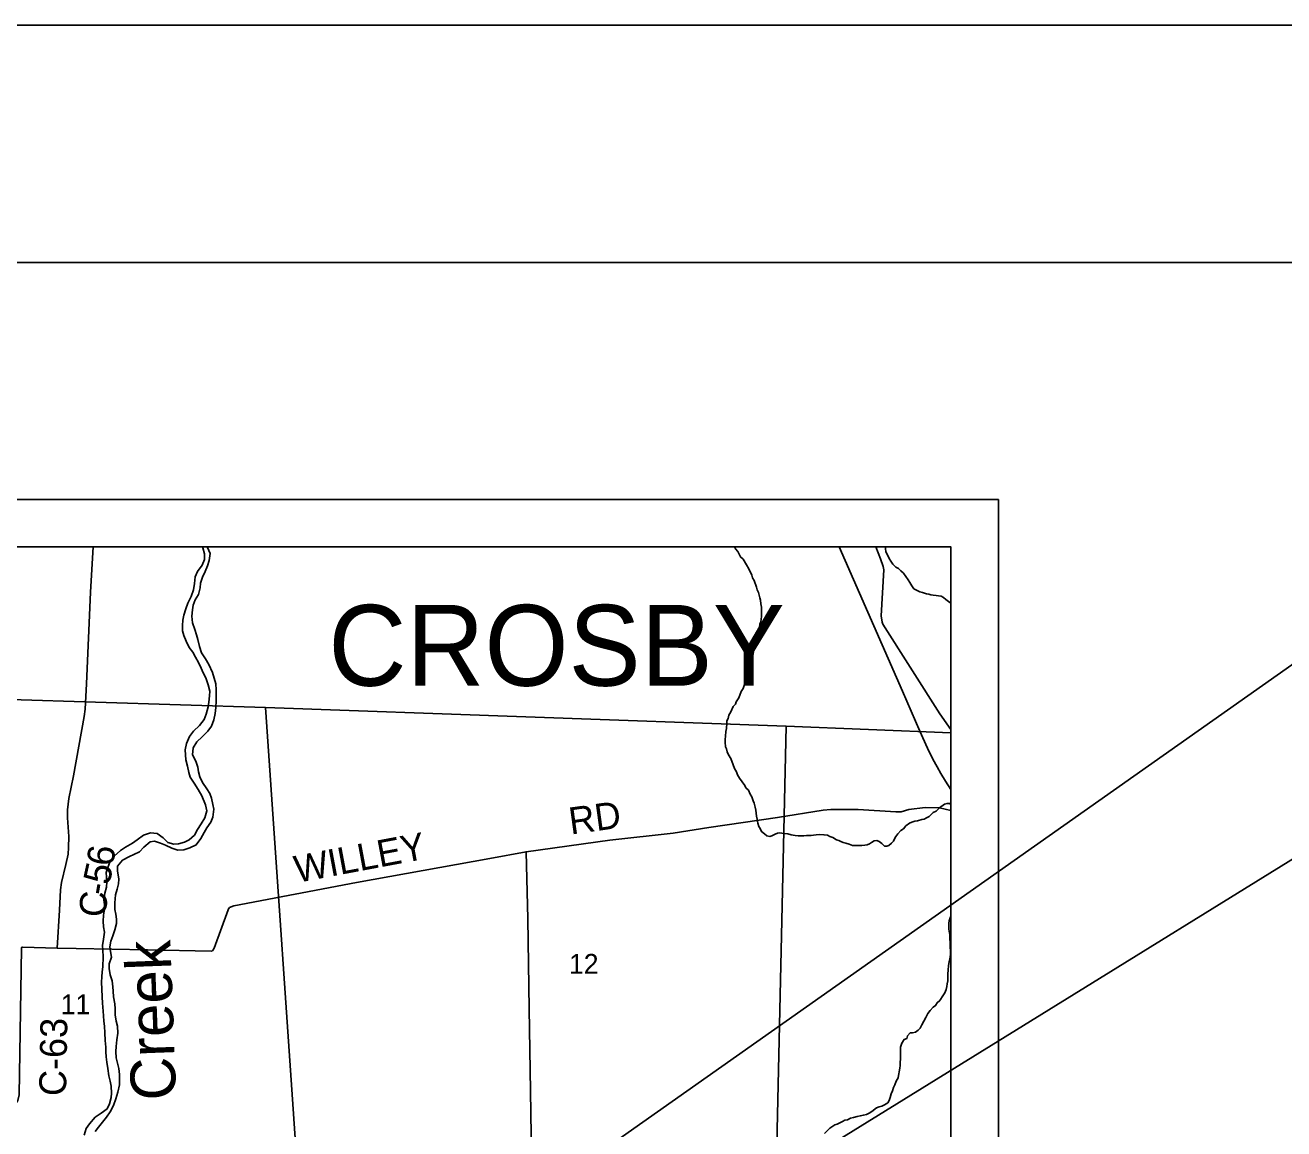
# Model space of a CAD drawing. Extents: x -7.5 to 26.5, y 3.5 to 25.5.
# Drawn here: x -0.509 to 2.145, y 23.173 to 25.5 of the extents above; entities that cross this region are included whole.
import ezdxf

# ---------------------------------------------------------------- set-up
doc = ezdxf.new("R2010")
doc.units = 0
for name, color, linetype in [('GM_X_Corporation', 7, 'Continuous'), ('GM_X_County_Road', 7, 'Continuous'), ('GM_X_County_Road_Text', 7, 'Continuous'), ('GM_X_Minor_River', 7, 'Continuous'), ('GM_X_Minor_River_Text', 7, 'Continuous'), ('GM_X_Rail_Line', 7, 'Continuous'), ('GM_X_Section_Text', 7, 'Continuous'), ('GM_X_Township_Text', 7, 'Continuous'), ('SH_Border', 7, 'Continuous'), ('SH_Cut_Line', 7, 'Continuous'), ('SH_Data', 7, 'Continuous'), ('SH_Text', 7, 'Continuous')]:
    doc.layers.add(name, color=color, linetype=linetype)

msp = doc.modelspace()

# ---------------------------------------------------------------- linework, layer by layer
at = {"layer": 'GM_X_Corporation'}
for points in [[(1.4431, 17.6), (1.4431, 24.4), (-5.1194, 24.4)], [(1.4431, 22.0759), (1.4431, 24.4), (-2.1213, 24.4), (-2.1683, 23.1094)]]:
    msp.add_lwpolyline(points, dxfattribs=at)
for points in [[(-0.8988, 24.09), (-0.0024, 24.0614), (0.0689, 23.0315), (-0.9291, 23.0451), (-0.9286, 23.0807)], [(-0.0024, 24.0614), (1.0957, 24.0219), (1.0735, 23.0136), (0.0689, 23.0315)], [(1.4431, 23.0021), (1.4431, 24.0081), (1.0957, 24.0219), (1.0735, 23.0136)]]:
    msp.add_lwpolyline(points, close=True, dxfattribs=at)
at = {"layer": 'GM_X_County_Road'}
msp.add_line((-0.4014, 23.5536), (-0.2509, 23.5505), dxfattribs=at)
for points in [[(-0.4415, 23.5545), (-0.4365, 23.6345), (-0.4346, 23.6771), (-0.4318, 23.6926), (-0.4232, 23.7303), (-0.418, 23.7526), (-0.4172, 23.7666), (-0.4169, 23.7894), (-0.4196, 23.8287), (-0.4195, 23.8461), (-0.4169, 23.87), (-0.4068, 23.9172), (-0.3843, 24.0428), (-0.3819, 24.0579), (-0.3793, 24.1114), (-0.3707, 24.305), (-0.3651, 24.4)], [(1.4431, 24.0155), (1.4193, 24.0482), (1.2993, 24.2371), (1.2979, 24.2416), (1.296, 24.2546), (1.3018, 24.3521), (1.3005, 24.359), (1.2945, 24.3752), (1.2846, 24.4)], [(-0.0809, 23.635), (-0.0806, 23.6359), (-0.0778, 23.6396), (-0.069, 23.6432), (0.19, 23.6929), (0.4706, 23.7431), (0.5472, 23.7576), (0.7239, 23.782), (0.8576, 23.7964), (0.9324, 23.8084), (1.0777, 23.8294), (1.1735, 23.8453), (1.1895, 23.8464), (1.2472, 23.8467), (1.3269, 23.8418), (1.3382, 23.8418), (1.354, 23.8467), (1.3886, 23.8511), (1.4186, 23.8498), (1.4431, 23.8442)], [(0.5601, 23.0196), (0.5565, 23.2538), (0.5539, 23.4264), (0.5513, 23.6162), (0.5472, 23.7576)], [(-0.2509, 23.5505), (-0.1165, 23.5476), (-0.1138, 23.5487), (-0.1103, 23.5539), (-0.0809, 23.635)], [(-0.7027, 23.1025), (-0.6986, 23.1032), (-0.6906, 23.1047), (-0.6779, 23.1104), (-0.6624, 23.1199), (-0.5287, 23.2271), (-0.5239, 23.2334), (-0.5217, 23.2447), (-0.5167, 23.5532), (-0.5166, 23.5545), (-0.5162, 23.5554), (-0.5157, 23.556), (-0.5147, 23.5562), (-0.4415, 23.5545), (-0.4014, 23.5536)]]:
    msp.add_lwpolyline(points, dxfattribs=at)
at = {"layer": 'GM_X_Minor_River'}
for points in [[(-0.1344, 24.4), (-0.1341, 24.3984), (-0.131, 24.3858), (-0.1305, 24.3736), (-0.1358, 24.3616), (-0.1456, 24.3485), (-0.15, 24.3368), (-0.1515, 24.3231), (-0.1541, 24.3099), (-0.1591, 24.2956), (-0.1659, 24.2813), (-0.1703, 24.2696), (-0.1745, 24.2564), (-0.1766, 24.2458), (-0.1773, 24.2347), (-0.1768, 24.2229), (-0.1744, 24.2134), (-0.1694, 24.2011), (-0.1629, 24.188), (-0.1555, 24.1779), (-0.1493, 24.1678), (-0.1435, 24.1567), (-0.1374, 24.1443), (-0.1334, 24.1347), (-0.128, 24.1239), (-0.1226, 24.1097), (-0.1196, 24.0959), (-0.1202, 24.0861), (-0.1217, 24.0728), (-0.1227, 24.0633), (-0.1272, 24.0474), (-0.1317, 24.0365), (-0.1415, 24.0238), (-0.154, 24.0116), (-0.1622, 24.0003), (-0.1683, 23.986), (-0.1713, 23.9724), (-0.1703, 23.9511), (-0.1665, 23.9377), (-0.1634, 23.9243), (-0.1606, 23.9147), (-0.1522, 23.9019), (-0.1441, 23.8888), (-0.1365, 23.8757), (-0.1286, 23.8564), (-0.1255, 23.8434), (-0.13, 23.8291), (-0.1376, 23.8163), (-0.1451, 23.8043), (-0.1515, 23.7927), (-0.1631, 23.7827), (-0.1727, 23.7776), (-0.1857, 23.7742), (-0.1956, 23.7736), (-0.2077, 23.777), (-0.2181, 23.7868), (-0.2304, 23.7958), (-0.2448, 23.7973), (-0.2594, 23.7927), (-0.2726, 23.7828), (-0.2826, 23.7758), (-0.2969, 23.7671), (-0.3081, 23.7601), (-0.3213, 23.7483), (-0.33, 23.7355), (-0.3348, 23.7242), (-0.3377, 23.714), (-0.3372, 23.7041), (-0.3363, 23.6938), (-0.3374, 23.6828), (-0.3407, 23.67), (-0.343, 23.656), (-0.3417, 23.6464), (-0.3412, 23.6365), (-0.3434, 23.6236), (-0.3441, 23.6111), (-0.3433, 23.5989), (-0.3417, 23.5878), (-0.3435, 23.573), (-0.3454, 23.5601), (-0.3449, 23.5502), (-0.3445, 23.5361), (-0.345, 23.5152), (-0.3464, 23.5046), (-0.3474, 23.4936), (-0.3477, 23.4826), (-0.3473, 23.4681)], [(-0.3314, 23.5115), (-0.3315, 23.5214), (-0.327, 23.5353), (-0.3286, 23.5475), (-0.3299, 23.5571), (-0.3281, 23.5692), (-0.3236, 23.5805), (-0.3195, 23.593), (-0.3161, 23.6062), (-0.3163, 23.6157), (-0.3175, 23.6256), (-0.3199, 23.636), (-0.32, 23.6497), (-0.318, 23.6664), (-0.3147, 23.6788), (-0.3117, 23.6898), (-0.3115, 23.6997), (-0.3141, 23.7173), (-0.3139, 23.7268), (-0.3033, 23.7398), (-0.289, 23.7478), (-0.2794, 23.7514), (-0.2675, 23.7576), (-0.2585, 23.7672), (-0.2453, 23.7783), (-0.2358, 23.7796), (-0.2233, 23.7759), (-0.2128, 23.7714), (-0.1997, 23.765), (-0.1868, 23.7609), (-0.1739, 23.7613), (-0.1616, 23.7659), (-0.1482, 23.7721), (-0.1384, 23.7851), (-0.1312, 23.7979), (-0.1256, 23.808), (-0.1173, 23.8196), (-0.1133, 23.8302), (-0.1113, 23.8472), (-0.113, 23.8568), (-0.1161, 23.8706), (-0.1192, 23.8805), (-0.1258, 23.8902), (-0.135, 23.9038), (-0.1408, 23.9157), (-0.1436, 23.9261), (-0.1448, 23.936), (-0.1491, 23.9483), (-0.156, 23.9621), (-0.1545, 23.9762), (-0.1469, 23.9893), (-0.1353, 23.9997), (-0.1236, 24.0116), (-0.1157, 24.0224), (-0.1108, 24.0356), (-0.1082, 24.0488), (-0.1068, 24.0614), (-0.106, 24.0754), (-0.1061, 24.0865), (-0.1058, 24.0986), (-0.1066, 24.1116), (-0.1102, 24.1231), (-0.1136, 24.1354), (-0.1216, 24.1519), (-0.1289, 24.1643), (-0.1369, 24.1767), (-0.1412, 24.1905), (-0.1446, 24.2046), (-0.1478, 24.215), (-0.1513, 24.2261), (-0.1559, 24.2403), (-0.1574, 24.254), (-0.156, 24.2677), (-0.1546, 24.2772), (-0.1501, 24.2885), (-0.143, 24.3001), (-0.1396, 24.3137), (-0.1393, 24.324), (-0.1349, 24.336), (-0.1292, 24.3481), (-0.124, 24.3601), (-0.1207, 24.3718), (-0.1188, 24.3859), (-0.1242, 24.3989), (-0.1242, 24.4)], [(1.0611, 23.7894), (1.055, 23.7907), (1.0501, 23.795), (1.0437, 23.8), (1.0408, 23.8062), (1.0378, 23.8108), (1.0361, 23.818), (1.0347, 23.8264), (1.0333, 23.8322), (1.0316, 23.8448), (1.0306, 23.8513), (1.0285, 23.8601), (1.0263, 23.8651), (1.023, 23.8735), (1.0197, 23.8789), (1.016, 23.8873), (1.0108, 23.8924), (1.0082, 23.897), (1.0026, 23.9051), (0.9971, 23.9128), (0.993, 23.9197), (0.9908, 23.9262), (0.9868, 23.9327), (0.9842, 23.9404), (0.9788, 23.9542), (0.9743, 23.9615), (0.9714, 23.968), (0.9696, 23.9742), (0.9678, 23.9788), (0.9672, 23.9883), (0.9673, 23.9944), (0.9678, 24.0009), (0.9684, 24.0108), (0.9696, 24.0176), (0.9706, 24.0282), (0.9707, 24.0332), (0.9731, 24.0385), (0.9751, 24.0457), (0.979, 24.0521), (0.9838, 24.0635), (0.9885, 24.0687), (0.9905, 24.0736), (0.9956, 24.0823), (1.0007, 24.0952), (1.0047, 24.1016), (1.0071, 24.108), (1.0083, 24.1153), (1.0108, 24.1259), (1.0144, 24.1334), (1.016, 24.1388), (1.018, 24.1467), (1.0196, 24.1513), (1.0217, 24.1604), (1.0241, 24.1683), (1.0258, 24.1748), (1.0275, 24.1847), (1.0299, 24.1907), (1.0319, 24.1987), (1.0341, 24.212), (1.0361, 24.218), (1.0377, 24.2241), (1.0394, 24.2306), (1.0402, 24.237), (1.0422, 24.2423), (1.0436, 24.2537), (1.0438, 24.2644), (1.0436, 24.2732), (1.0425, 24.28), (1.0412, 24.2881), (1.0401, 24.2927), (1.0373, 24.3041), (1.0343, 24.3099), (1.0329, 24.3156), (1.0282, 24.3294), (1.0249, 24.3348), (1.0231, 24.3405), (1.0172, 24.3536), (1.012, 24.3624), (1.005, 24.374), (0.9994, 24.379), (0.9939, 24.3905), (0.9887, 24.3963), (0.9869, 24.4)], [(1.3048, 24.4), (1.305, 24.3958), (1.306, 24.3905), (1.3079, 24.3855), (1.3104, 24.3809), (1.3126, 24.3755), (1.316, 24.3701), (1.3208, 24.3639), (1.3271, 24.3577), (1.3324, 24.3546), (1.3377, 24.35), (1.3433, 24.3445), (1.3481, 24.338), (1.3529, 24.331), (1.3563, 24.3253), (1.3607, 24.3183), (1.3651, 24.3118), (1.3715, 24.3079), (1.3772, 24.3055), (1.3833, 24.3039), (1.3912, 24.3015), (1.3962, 24.3006), (1.4007, 24.2994), (1.4056, 24.2986), (1.4117, 24.2977), (1.417, 24.2969), (1.4227, 24.296), (1.4276, 24.2937), (1.4325, 24.2894), (1.4378, 24.2851), (1.4431, 24.2814)], [(1.4431, 23.857), (1.4403, 23.8592), (1.435, 23.8592), (1.4296, 23.8578), (1.4188, 23.8504), (1.4122, 23.8432), (1.4057, 23.8399), (1.3968, 23.832), (1.3914, 23.8291), (1.3864, 23.8261), (1.3815, 23.8254), (1.3727, 23.8229), (1.3666, 23.8219), (1.3608, 23.8197), (1.3558, 23.8175), (1.3481, 23.8119), (1.3427, 23.8055), (1.3377, 23.8025), (1.331, 23.795), (1.3271, 23.7897), (1.324, 23.7845), (1.3216, 23.7799), (1.3177, 23.7754), (1.3123, 23.7709), (1.3077, 23.7691), (1.3032, 23.7695), (1.2972, 23.775), (1.2919, 23.7789), (1.287, 23.7812), (1.2813, 23.7806), (1.2759, 23.7772), (1.2713, 23.7743), (1.2663, 23.772), (1.2617, 23.7714), (1.2549, 23.7707), (1.2465, 23.7705), (1.2411, 23.7705), (1.2358, 23.771), (1.2283, 23.7738), (1.2211, 23.7754), (1.2161, 23.777), (1.2112, 23.779), (1.2067, 23.781), (1.2018, 23.7826), (1.1942, 23.7873), (1.1878, 23.7897), (1.1825, 23.7921), (1.1753, 23.7933), (1.1654, 23.7935), (1.1589, 23.7928), (1.1532, 23.7925), (1.1486, 23.7918), (1.1433, 23.7915), (1.1384, 23.7916), (1.133, 23.7913), (1.1266, 23.7911), (1.1208, 23.7911), (1.1144, 23.792), (1.1064, 23.7933), (1.0992, 23.7949), (1.0916, 23.7962), (1.0863, 23.7967), (1.0817, 23.7971), (1.0772, 23.7964), (1.0726, 23.7946), (1.0657, 23.7913), (1.0611, 23.7894)], [(1.4431, 23.6215), (1.4424, 23.6203), (1.4393, 23.6119), (1.4384, 23.607), (1.4383, 23.6001), (1.4386, 23.5944), (1.4392, 23.5898), (1.4406, 23.583), (1.4409, 23.5746), (1.4411, 23.5658), (1.4417, 23.5555), (1.4419, 23.5487), (1.4422, 23.5422), (1.4413, 23.5353), (1.4396, 23.5251), (1.4379, 23.5179), (1.4374, 23.5076), (1.4368, 23.5004), (1.4367, 23.4912), (1.4362, 23.4851), (1.4353, 23.479), (1.4345, 23.4733), (1.4328, 23.4673), (1.43, 23.4601), (1.4261, 23.454), (1.4195, 23.4442), (1.414, 23.439), (1.4105, 23.4333), (1.4055, 23.43), (1.3993, 23.4229), (1.3942, 23.4168), (1.3899, 23.4082), (1.382, 23.3923), (1.378, 23.3855), (1.3738, 23.381), (1.368, 23.3773), (1.3619, 23.3758), (1.3573, 23.3755), (1.3515, 23.3692), (1.3499, 23.3635), (1.3441, 23.3616), (1.3394, 23.3537), (1.337, 23.3458), (1.3365, 23.3206), (1.336, 23.313), (1.3359, 23.3062), (1.3354, 23.3016), (1.3349, 23.297), (1.3328, 23.2856), (1.3316, 23.2807), (1.3277, 23.2735), (1.3249, 23.2663), (1.3221, 23.2607), (1.3197, 23.2535), (1.3173, 23.247), (1.3152, 23.2391), (1.3125, 23.2334), (1.3097, 23.2285), (1.3028, 23.2236), (1.297, 23.2211), (1.292, 23.22), (1.2863, 23.2178), (1.2763, 23.21), (1.2705, 23.2066), (1.2647, 23.2037), (1.2586, 23.2023), (1.2517, 23.2005), (1.2452, 23.1994), (1.2379, 23.1969), (1.2315, 23.1955), (1.2249, 23.1925), (1.2192, 23.1915), (1.2142, 23.1889), (1.2088, 23.1863), (1.2031, 23.1833), (1.1985, 23.1819), (1.1938, 23.1789), (1.1877, 23.1744), (1.1764, 23.1636)], [(-0.3613, 23.1675), (-0.3542, 23.1772), (-0.346, 23.1876), (-0.337, 23.1981), (-0.3295, 23.2093), (-0.3223, 23.2224), (-0.3174, 23.2368), (-0.3132, 23.2504), (-0.3102, 23.2663), (-0.3096, 23.2879), (-0.3116, 23.3005), (-0.3144, 23.3116), (-0.3167, 23.3227), (-0.3179, 23.3361), (-0.3169, 23.3471), (-0.3154, 23.3611), (-0.3132, 23.3752), (-0.3143, 23.3896), (-0.3171, 23.4), (-0.319, 23.4134), (-0.3187, 23.4263), (-0.3196, 23.437), (-0.3226, 23.4515), (-0.3231, 23.4633), (-0.324, 23.4728), (-0.3256, 23.4854), (-0.3298, 23.4981), (-0.3314, 23.5115)], [(-0.3473, 23.4681), (-0.3466, 23.4513), (-0.3454, 23.4384), (-0.3443, 23.4216), (-0.3438, 23.4117), (-0.3429, 23.4006), (-0.3413, 23.3899), (-0.3409, 23.3755), (-0.3398, 23.3595), (-0.3386, 23.3457), (-0.3385, 23.3355), (-0.338, 23.3248), (-0.3364, 23.3137), (-0.3348, 23.3004), (-0.3321, 23.2851), (-0.3294, 23.2736), (-0.3273, 23.2636), (-0.3266, 23.2488), (-0.3276, 23.2393), (-0.331, 23.2257), (-0.3361, 23.2155), (-0.3485, 23.2067), (-0.3609, 23.1979), (-0.3734, 23.1841), (-0.3798, 23.174), (-0.3843, 23.1601)]]:
    msp.add_lwpolyline(points, dxfattribs=at)
at = {"layer": 'GM_X_Rail_Line'}
msp.add_lwpolyline([(1.4431, 23.8888), (1.4315, 23.9065), (1.422, 23.9224), (1.414, 23.9366), (1.4051, 23.9526), (1.3939, 23.9755), (1.3778, 24.0118), (1.3406, 24.0963), (1.2075, 24.4)], dxfattribs=at)
at = {"layer": 'SH_Border'}
msp.add_lwpolyline([(-5.9569, 25), (26.0431, 25), (26.0431, 4), (-5.9569, 4)], close=True, dxfattribs=at)
at = {"layer": 'SH_Cut_Line'}
msp.add_lwpolyline([(-7.4569, 3.5), (26.5431, 3.5), (26.5431, 25.5), (-7.4569, 25.5)], close=True, dxfattribs=at)
at = {"layer": 'SH_Data'}
for p, q in [((-5.4569, 24.5), (1.5431, 24.5)), ((1.5431, 24.5), (1.5431, 17.5)), ((-5.3569, 24.4), (1.4431, 24.4)), ((1.4431, 24.4), (1.4431, 17.6))]:
    msp.add_line(p, q, dxfattribs=at)
at = {"layer": 'SH_Text'}
msp.add_lwpolyline([(2.4449, 24.351), (-2.5961, 20.7995), (2.4449, 23.9163)], close=True, dxfattribs=at)

# ---------------------------------------------------------------- texts
at = {"layer": 'GM_X_County_Road_Text'}
for s, height, rotation, p in [('RD', 0.05682, 7.854, (0.6415, 23.7936)), ('WILLEY', 0.05682, 10.608, (0.0644, 23.6918)), ('6', 0.0568, 82.8428, (-0.3231, 23.7255)), ('5', 0.0568, 77.5359, (-0.3317, 23.6856)), ('C', 0.0568, 85.9049, (-0.3386, 23.6182)), ('-', 0.0568, 80.3869, (-0.3354, 23.6633)), ('C-63', 0.05682, 88.9654, (-0.4226, 23.2421))]:
    msp.add_text(s, height=height, rotation=rotation, dxfattribs=at).set_placement(p)
at = {"layer": 'GM_X_Minor_River_Text'}
msp.add_text('Creek', height=0.0947, rotation=92.1301, dxfattribs=at).set_placement((-0.1902, 23.2349))
at = {"layer": 'GM_X_Section_Text'}
for s, p in [('12', (0.6378, 23.5002)), ('11', (-0.4338, 23.4149))]:
    msp.add_text(s, height=0.04186, rotation=0, dxfattribs=at).set_placement(p)
at = {"layer": 'GM_X_Township_Text'}
msp.add_text('CROSBY', height=0.17045, rotation=0, dxfattribs=at).set_placement((0.1304, 24.1074))

doc.saveas('drawing.dxf')
